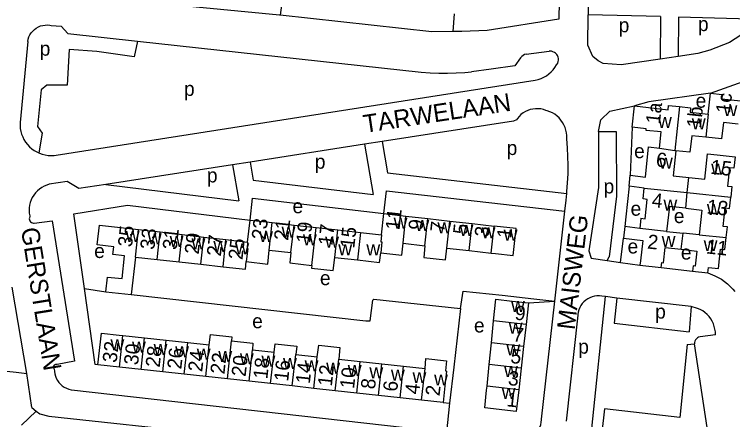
# Model space of a CAD drawing. Extents: x 161936 to 163647, y 386450 to 388633.
# Drawn here: x 162668.3 to 162869.1, y 387499.8 to 387613.3 of the extents above; entities that cross this region are included whole.
import ezdxf

# ---------------------------------------------------------------- set-up
doc = ezdxf.new("R2010")
doc.units = 0
for name, color, linetype in [('BLT_Basislijn', 7, 'Continuous'), ('BLT_Bebouwing', 7, 'Continuous'), ('BLT_Centroide', 7, 'Continuous'), ('BLT_Huisnummer', 7, 'Continuous'), ('BLT_Huisnummer_ tussenligend', 7, 'Continuous'), ('BLT_Onderverdeling_panden', 7, 'Continuous'), ('BLT_Straatnaam', 7, 'Continuous'), ('BLT_Vlakafsluiter', 7, 'Continuous')]:
    doc.layers.add(name, color=color, linetype=linetype)

msp = doc.modelspace()

# ---------------------------------------------------------------- linework, layer by layer
at = {"layer": 'BLT_Basislijn'}
for p, q in [((162743.31, 387618.68), (162742.58, 387613.02)), ((162828.78, 387617.69), (162828.68, 387613.16)), ((162790.95, 387608.44), (162791.33, 387613.38)), ((162848.91, 387612.62), (162828.68, 387613.16)), ((162848.91, 387612.62), (162848.83, 387600.77)), ((162853.91, 387612.48), (162853.84, 387601.51)), ((162672, 387605.68), (162669.87, 387583.02)), ((162702.71, 387605.79), (162782.04, 387597.12)), ((162811.38, 387602.17), (162817.8, 387602.93)), ((162853.84, 387601.51), (162848.83, 387600.77)), ((162679.94, 387573.88), (162813.91, 387594.86)), ((162766.13, 387576.91), (162734.19, 387571.94)), ((162771.08, 387577.68), (162766.13, 387576.91)), ((162766.13, 387576.91), (162768.57, 387562.84)), ((162771.08, 387577.68), (162772.59, 387568.91)), ((162734.19, 387571.94), (162729.25, 387571.17)), ((162734.19, 387571.94), (162735.06, 387566.88)), ((162729.25, 387571.17), (162693.83, 387565.67)), ((162729.25, 387571.17), (162730.99, 387561.05)), ((162772.59, 387568.91), (162822.7, 387563.16)), ((162735.06, 387566.88), (162768.57, 387562.84)), ((162693.83, 387565.67), (162730.99, 387561.05)), ((162822.49, 387561.28), (162822.7, 387563.16)), ((162822.14, 387558.19), (162822.49, 387561.28)), ((162819.34, 387532.99), (162822.14, 387558.19)), ((162837.74, 387543.83), (162838.58, 387550.62)), ((162833.95, 387544.36), (162834.57, 387545.42)), ((162833.95, 387544.36), (162837.74, 387543.83)), ((162837.74, 387543.83), (162843.17, 387543.06)), ((162849.13, 387542.39), (162857.84, 387541.42)), ((162671.73, 387512.76), (162667.69, 387536.93)), ((162829.67, 387497.33), (162833.54, 387534.27)), ((162833.54, 387534.27), (162832.48, 387534.39)), ((162836.74, 387533.89), (162833.54, 387534.27)), ((162836.74, 387533.89), (162835.93, 387526.84)), ((162857.52, 387531.55), (162836.74, 387533.89)), ((162815.66, 387499.97), (162819.34, 387532.99)), ((162857.52, 387531.55), (162856.92, 387524.43)), ((162825.8, 387529.05), (162822.49, 387499.42)), ((162835.93, 387526.84), (162856.92, 387524.43)), ((162864.26, 387523.62), (162859.95, 387523)), ((162856.37, 387520.88), (162858.36, 387521.03)), ((162861.93, 387497.67), (162858.36, 387521.03)), ((162673.18, 387503.23), (162671.73, 387512.76)), ((162684.27, 387508.21), (162789.12, 387496.33)), ((162788.15, 387504.68), (162789.94, 387504.45)), ((162670.29, 387498.35), (162674.4, 387502.25)), ((162673.18, 387503.23), (162674.4, 387502.25))]:
    msp.add_line(p, q, dxfattribs=at)
for points in [[(162796.15, 387657.6), (162798.19, 387657.39), (162818.08, 387655.25), (162820.47, 387653.11), (162821.27, 387651.11), (162820.44, 387611.92), (162800.48, 387608.77), (162793.38, 387608.47), (162790.95, 387608.44)], [(162742.58, 387613.02), (162742.44, 387613.03), (162667.7, 387620.29)], [(162790.95, 387608.44), (162784.97, 387608.38), (162742.58, 387613.02)], [(162848.83, 387600.77), (162837.92, 387599.14), (162832.86, 387599.51), (162831.52, 387600.27), (162830.02, 387601.45), (162828.56, 387604.68), (162828.68, 387613.16)], [(162876.09, 387610.55), (162874.08, 387611.94), (162853.91, 387612.48)], [(162672, 387605.68), (162672.13, 387606.33), (162672.34, 387606.95), (162672.62, 387607.54), (162672.98, 387608.09), (162673.4, 387608.6), (162673.88, 387609.05), (162674.4, 387609.44), (162674.98, 387609.76), (162675.58, 387610.01), (162676.22, 387610.18), (162676.87, 387610.28), (162677.52, 387610.3), (162678.18, 387610.23), (162678.52, 387610.17)], [(162678.52, 387610.17), (162681.37, 387609.97), (162683.2, 387607.93), (162702.71, 387605.79)], [(162876.09, 387610.55), (162868.22, 387605.43), (162862.65, 387603.23), (162859.31, 387602.33), (162853.84, 387601.51)], [(162702.71, 387605.79), (162701.75, 387601.4), (162691.33, 387602.86), (162683.61, 387603.44), (162683.01, 387593.48), (162677.37, 387593.42), (162675.74, 387592.18), (162674.71, 387581.89), (162676.02, 387580.02), (162675.15, 387574.47)], [(162811.38, 387602.17), (162810.93, 387602.01), (162810.52, 387601.78), (162810.14, 387601.48), (162809.8, 387601.1)], [(162819.94, 387599.26), (162820.16, 387599.63), (162820.31, 387600.04), (162820.38, 387600.46), (162820.37, 387600.89), (162820.28, 387601.31), (162820.12, 387601.71), (162819.88, 387602.07), (162819.59, 387602.38), (162819.24, 387602.63), (162818.85, 387602.81), (162818.43, 387602.92), (162818, 387602.95), (162817.8, 387602.93)], [(162809.8, 387601.1), (162808.17, 387598.85), (162801.6, 387597.89), (162796.1, 387597.17)], [(162862.91, 387591.19), (162875.97, 387595.89), (162884.46, 387600.33), (162888.82, 387601.21), (162889.7, 387601.21)], [(162813.91, 387594.86), (162814.73, 387595.06), (162815.52, 387595.33), (162816.28, 387595.68), (162817, 387596.1), (162817.68, 387596.59), (162818.31, 387597.14), (162818.89, 387597.74), (162819.4, 387598.4), (162819.86, 387599.11), (162819.94, 387599.26)], [(162782.04, 387597.12), (162784.48, 387596.94), (162786.92, 387596.84), (162789.36, 387596.82), (162791.8, 387596.87), (162794.24, 387597.01), (162796.1, 387597.17)], [(162862.91, 387591.19), (162845.67, 387588.78), (162841.59, 387587.63)], [(162816.86, 387586.4), (162816.16, 387586.64), (162815.43, 387586.79), (162814.7, 387586.87), (162813.96, 387586.86), (162813.22, 387586.78), (162812.5, 387586.62), (162811.8, 387586.38), (162811.12, 387586.07), (162810.49, 387585.68), (162809.9, 387585.23), (162809.37, 387584.72), (162808.89, 387584.16), (162808.62, 387583.79)], [(162822.69, 387578.56), (162822.69, 387579.35), (162822.61, 387580.13), (162822.45, 387580.89), (162822.21, 387581.64), (162821.9, 387582.36), (162821.51, 387583.04), (162821.06, 387583.68), (162820.55, 387584.28), (162819.97, 387584.81), (162819.35, 387585.29), (162818.68, 387585.7), (162817.98, 387586.03), (162817.24, 387586.3), (162816.86, 387586.4)], [(162831.53, 387580.5), (162832.25, 387583.72), (162834.73, 387586.17), (162841.59, 387587.63)], [(162808.62, 387583.79), (162807.82, 387583.39), (162771.08, 387577.68)], [(162669.87, 387583.02), (162669.86, 387582.19), (162669.92, 387581.35), (162670.07, 387580.53), (162670.3, 387579.73), (162670.6, 387578.95), (162670.97, 387578.2), (162671.42, 387577.5), (162671.92, 387576.84), (162672.49, 387576.23), (162673.12, 387575.68), (162673.8, 387575.19), (162674.52, 387574.76), (162675.15, 387574.47)], [(162831.53, 387580.5), (162831.61, 387564.84), (162828.88, 387547.07), (162829.54, 387545.03), (162833.95, 387544.36)], [(162831.53, 387580.5), (162836.5, 387580.52), (162836.62, 387562.37), (162834.57, 387545.42)], [(162840.96, 387581.68), (162840.46, 387568.22)], [(162822.7, 387563.16), (162822.76, 387563.71), (162822.95, 387566.16), (162823.06, 387568.6), (162823.09, 387571.05), (162823.04, 387573.5), (162822.91, 387575.95), (162822.71, 387578.39), (162822.69, 387578.56)], [(162675.15, 387574.47), (162675.27, 387574.41), (162676.06, 387574.13), (162676.87, 387573.93), (162677.7, 387573.81), (162678.53, 387573.77), (162679.36, 387573.8), (162679.94, 387573.88)], [(162678.04, 387565.7), (162677.31, 387565.48), (162676.6, 387565.18), (162675.92, 387564.82), (162675.29, 387564.38), (162674.7, 387563.88), (162674.17, 387563.32), (162673.7, 387562.71), (162673.3, 387562.06), (162672.96, 387561.36), (162672.7, 387560.64), (162672.52, 387559.89), (162672.41, 387559.13), (162672.39, 387558.36), (162672.44, 387557.6), (162672.58, 387556.84), (162672.62, 387556.66)], [(162693.83, 387565.67), (162686.28, 387564.49), (162683.07, 387566.5), (162678.04, 387565.7)], [(162771.56, 387557.51), (162772.3, 387563.91), (162822.14, 387558.19)], [(162840.11, 387565.17), (162839.23, 387556.63), (162838.95, 387553.9)], [(162734.16, 387555.66), (162734.85, 387561.87), (162771.56, 387557.51)], [(162687.86, 387536.56), (162684.87, 387557.46), (162699.94, 387559.87), (162734.16, 387555.66)], [(162672.62, 387556.66), (162672.5, 387556.37), (162672.46, 387556.06), (162672.5, 387555.75), (162672.61, 387555.46), (162672.8, 387555.21), (162673.04, 387555.02), (162673.32, 387554.89), (162673.63, 387554.84), (162673.82, 387554.85)], [(162673.82, 387554.85), (162678.85, 387555.45), (162685.07, 387516.25), (162680.25, 387515.25)], [(162862.14, 387540.94), (162864.05, 387540.13), (162865, 387539.67), (162865.92, 387539.14), (162866.79, 387538.54), (162867.62, 387537.87), (162868.4, 387537.15), (162869.11, 387536.37), (162869.66, 387535.69)], [(162691.64, 387515.16), (162690.9, 387515.25), (162687.86, 387536.56)], [(162687.86, 387536.56), (162693.82, 387535.64)], [(162793.03, 387530.99), (162793.71, 387535.83), (162804.67, 387534.64), (162813.46, 387533.64), (162819.34, 387532.99)], [(162700.95, 387534.86), (162766.51, 387527.54), (162767.78, 387527.49), (162768.48, 387533.25), (162768.73, 387533.53), (162793.03, 387530.99)], [(162832.48, 387534.39), (162831.81, 387534.47), (162831.14, 387534.46), (162830.46, 387534.38), (162829.81, 387534.22), (162829.18, 387533.98), (162828.58, 387533.67), (162828.02, 387533.29), (162827.51, 387532.84), (162827.05, 387532.34), (162826.66, 387531.79), (162826.34, 387531.2), (162826.09, 387530.57), (162825.91, 387529.92), (162825.81, 387529.25), (162825.8, 387529.05)], [(162864.26, 387523.62), (162864.24, 387524.41), (162864.13, 387525.18), (162863.94, 387525.95), (162863.68, 387526.69), (162863.34, 387527.41), (162862.93, 387528.08), (162862.46, 387528.71), (162861.93, 387529.29), (162861.34, 387529.81), (162860.7, 387530.27), (162860.01, 387530.66), (162859.29, 387530.98), (162857.52, 387531.55)], [(162793.03, 387530.99), (162791.14, 387514.5), (162789.94, 387504.45)], [(162859.95, 387523), (162859.57, 387522.89), (162859.22, 387522.71), (162858.92, 387522.45), (162858.67, 387522.15), (162858.49, 387521.79), (162858.38, 387521.41), (162858.36, 387521.03)], [(162856.37, 387520.88), (162854.26, 387500.47), (162833.24, 387502.91), (162832.51, 387496.26)], [(162648.95, 387510.13), (162649.61, 387515.1), (162660.06, 387514.06), (162668.81, 387513.1), (162671.73, 387512.76)], [(162680.25, 387515.25), (162680.02, 387515.32), (162679.78, 387515.31), (162679.56, 387515.22), (162679.37, 387515.06), (162679.25, 387514.85), (162679.2, 387514.62), (162679.23, 387514.38), (162679.34, 387514.16), (162679.45, 387514.04)], [(162679.45, 387514.04), (162679.47, 387513.37), (162679.57, 387512.7), (162679.74, 387512.04), (162680, 387511.42), (162680.32, 387510.82), (162680.72, 387510.27), (162681.17, 387509.77), (162681.68, 387509.33), (162682.24, 387508.95), (162682.85, 387508.64), (162683.48, 387508.4), (162684.14, 387508.24), (162684.27, 387508.21)], [(162789.94, 387504.45), (162789.12, 387496.33)], [(162674.4, 387502.25), (162675.36, 387501.47), (162677.9, 387500.85), (162722.89, 387495.99), (162725.51, 387494.85), (162727.19, 387492.41), (162727.19, 387489.31)], [(162808.42, 387494.15), (162809.11, 387494.05), (162809.81, 387494.03), (162810.5, 387494.09), (162811.18, 387494.23), (162811.84, 387494.45), (162812.47, 387494.74), (162813.06, 387495.1), (162813.61, 387495.53), (162814.1, 387496.02), (162814.54, 387496.56), (162814.91, 387497.15), (162815.21, 387497.78), (162815.43, 387498.43), (162815.58, 387499.11), (162815.65, 387499.8), (162815.66, 387499.97)]]:
    msp.add_lwpolyline(points, dxfattribs=at)
at = {"layer": 'BLT_Bebouwing'}
for p, q in [((162862.26, 387585.33), (162862.91, 387591.19)), ((162840.96, 387581.68), (162841.59, 387587.63)), ((162733.48, 387549.55), (162734.16, 387555.66)), ((162734.16, 387555.66), (162740.33, 387554.98)), ((162770.9, 387551.59), (162771.56, 387557.51)), ((162771.56, 387557.51), (162777.75, 387556.83)), ((162777.75, 387556.83), (162783.87, 387556.15)), ((162783.87, 387556.15), (162790.05, 387555.39)), ((162843.4, 387556.19), (162843.08, 387553.37)), ((162740.33, 387554.98), (162746.45, 387554.3)), ((162746.45, 387554.3), (162752.64, 387553.61)), ((162790.05, 387555.39), (162796.22, 387554.71)), ((162796.22, 387554.71), (162802.39, 387554.02)), ((162843.08, 387553.37), (162838.95, 387553.9)), ((162702.96, 387553.06), (162709.04, 387552.38)), ((162709.04, 387552.38), (162715.22, 387551.68)), ((162715.22, 387551.68), (162721.27, 387550.94)), ((162752.64, 387553.61), (162758.68, 387552.93)), ((162758.68, 387552.93), (162765.03, 387552.24)), ((162765.03, 387552.24), (162770.9, 387551.59)), ((162850.62, 387552.52), (162855.24, 387552)), ((162859.67, 387551.56), (162855.24, 387552)), ((162721.27, 387550.94), (162727.37, 387550.23)), ((162727.37, 387550.23), (162733.48, 387549.55)), ((162776.94, 387549.19), (162783.04, 387548.52)), ((162789.21, 387547.83), (162795.38, 387547.15)), ((162739.53, 387547.27), (162745.61, 387546.59)), ((162795.38, 387547.15), (162801.56, 387546.47)), ((162702.11, 387545.36), (162708.19, 387544.69)), ((162708.19, 387544.69), (162714.37, 387544)), ((162714.37, 387544), (162720.45, 387543.33)), ((162757.84, 387545.24), (162764.19, 387544.53)), ((162843.31, 387544.32), (162843.17, 387543.06)), ((162720.45, 387543.33), (162726.61, 387542.65)), ((162843.17, 387543.06), (162849.13, 387542.39)), ((162862.31, 387542.41), (162865.11, 387542.11)), ((162693.82, 387535.64), (162700.95, 387534.86)), ((162801.65, 387521.37), (162802.26, 387527.46)), ((162811.34, 387526.43), (162810.65, 387520.35)), ((162691.64, 387515.16), (162692.61, 387524.04)), ((162698.64, 387523.38), (162704.67, 387522.72)), ((162704.67, 387522.72), (162710.7, 387522.06)), ((162710.7, 387522.06), (162716.73, 387521.4)), ((162716.73, 387521.4), (162722.76, 387520.74)), ((162801.03, 387515.29), (162801.65, 387521.37)), ((162810.65, 387520.35), (162809.97, 387514.28)), ((162734.83, 387519.41), (162740.89, 387518.75)), ((162746.97, 387518.08), (162752.92, 387517.43)), ((162758.95, 387516.77), (162764.98, 387516.11)), ((162764.98, 387516.11), (162771.01, 387515.45)), ((162697.68, 387514.51), (162691.64, 387515.16)), ((162703.71, 387513.85), (162697.68, 387514.51)), ((162709.74, 387513.2), (162703.71, 387513.85)), ((162771.01, 387515.45), (162777.05, 387514.79)), ((162777.05, 387514.79), (162783.08, 387514.12)), ((162800.41, 387509.2), (162801.03, 387515.29)), ((162809.97, 387514.28), (162809.28, 387508.2)), ((162715.77, 387512.54), (162709.74, 387513.2)), ((162721.8, 387511.89), (162715.77, 387512.54)), ((162727.84, 387511.23), (162721.8, 387511.89)), ((162733.87, 387510.58), (162727.84, 387511.23)), ((162739.9, 387509.92), (162733.87, 387510.58)), ((162745.93, 387509.27), (162739.9, 387509.92)), ((162751.96, 387508.61), (162745.93, 387509.27)), ((162757.99, 387507.96), (162751.96, 387508.61)), ((162764.03, 387507.3), (162757.99, 387507.96)), ((162770.06, 387506.65), (162764.03, 387507.3)), ((162776.09, 387505.99), (162770.06, 387506.65)), ((162782.12, 387505.34), (162776.09, 387505.99))]:
    msp.add_line(p, q, dxfattribs=at)
for points in [[(162862.91, 387591.19), (162866.17, 387590.83), (162866.04, 387589.6), (162871.31, 387589.02)], [(162841.59, 387587.63), (162851.04, 387586.58), (162851.18, 387587.8), (162854.25, 387587.46)], [(162854.25, 387587.46), (162857.33, 387587.11), (162857.2, 387585.89), (162862.26, 387585.33)], [(162870.59, 387582.55), (162866.48, 387583), (162865.98, 387578.39), (162861.54, 387578.87)], [(162848.6, 387575.86), (162849.07, 387580.36), (162844.87, 387580.81), (162844.92, 387581.26), (162840.96, 387581.68)], [(162861.54, 387578.87), (162857.63, 387579.29), (162857.13, 387574.69), (162853.19, 387575.12)], [(162840.46, 387568.22), (162844.7, 387567.75), (162845.59, 387576.18), (162848.6, 387575.86)], [(162853.19, 387575.12), (162852.43, 387568.1), (162856.82, 387567.62)], [(162856.82, 387567.62), (162861.28, 387567.14), (162862.05, 387574.27), (162864.78, 387573.97), (162869.75, 387573.43), (162869.4, 387570.23), (162868.18, 387570.36), (162867.62, 387565.22), (162868.84, 387565.09), (162868.52, 387562.12)], [(162840.11, 387565.17), (162840.46, 387568.22)], [(162844.37, 387564.67), (162840.11, 387565.17)], [(162843.4, 387556.19), (162844.64, 387556.06), (162845.21, 387561.48), (162844.05, 387561.6), (162844.37, 387564.67)], [(162867.29, 387550.82), (162867.62, 387553.8), (162866.4, 387553.93), (162866.95, 387559.08), (162868.18, 387558.94), (162868.52, 387562.12)], [(162855.96, 387559), (162851.39, 387559.5), (162850.62, 387552.52)], [(162855.96, 387559), (162860.41, 387558.51), (162859.67, 387551.56)], [(162693.82, 387535.64), (162694.27, 387539.76), (162698.37, 387539.31), (162699.07, 387545.7), (162695.84, 387546.05), (162696.08, 387548.23), (162691.45, 387548.75), (162692.06, 387554.27), (162702.96, 387553.06)], [(162801.56, 387546.47), (162802.75, 387546.33), (162807.72, 387545.78), (162808.56, 387553.34), (162802.39, 387554.02)], [(162838.95, 387553.9), (162838.58, 387550.62)], [(162838.58, 387550.62), (162843.94, 387549.96), (162843.31, 387544.32)], [(162865.11, 387542.11), (162865.7, 387547.56), (162866.93, 387547.43), (162867.29, 387550.82)], [(162770.69, 387546.57), (162776.59, 387545.92), (162776.94, 387549.19)], [(162783.04, 387548.52), (162782.71, 387545.24), (162788.8, 387544.57), (162789.21, 387547.83)], [(162849.77, 387543.77), (162850.23, 387548), (162854.65, 387547.52)], [(162733.12, 387544.06), (162739.13, 387543.39), (162739.53, 387547.27)], [(162745.61, 387546.59), (162745.31, 387543.71), (162751.42, 387543.03)], [(162764.19, 387544.53), (162770.38, 387543.85), (162770.69, 387546.57)], [(162854.65, 387547.52), (162859.07, 387547.04), (162858.61, 387542.81), (162858, 387542.85), (162857.84, 387541.42)], [(162702.11, 387545.36), (162700.95, 387534.86)], [(162726.61, 387542.65), (162732.89, 387541.95), (162733.12, 387544.06)], [(162751.42, 387543.03), (162751.33, 387542.24), (162757.44, 387541.56), (162757.84, 387545.24)], [(162849.13, 387542.39), (162849.29, 387543.82), (162849.77, 387543.77)], [(162862.14, 387540.94), (162862.31, 387542.41)], [(162857.84, 387541.42), (162862.14, 387540.94)], [(162802.26, 387527.46), (162802.88, 387533.54), (162807.43, 387533.02), (162812.03, 387532.5)], [(162812.03, 387532.5), (162811.34, 387526.43)], [(162692.61, 387524.04), (162697.58, 387523.5), (162698.64, 387523.38)], [(162722.76, 387520.74), (162723.08, 387523.68), (162729.08, 387523.02), (162729, 387521.93)], [(162729, 387521.93), (162734.98, 387521.27), (162734.83, 387519.41)], [(162740.89, 387518.75), (162741.15, 387521.09), (162747.23, 387520.43), (162746.97, 387518.08)], [(162752.92, 387517.43), (162753.38, 387520.7), (162759.22, 387520.06), (162758.95, 387516.77)], [(162783.08, 387514.12), (162783.31, 387516.92), (162789.11, 387516.28), (162788.8, 387513.5), (162789.11, 387513.46), (162788.65, 387509.28), (162788.15, 387504.68)], [(162799.79, 387503.12), (162800.3, 387508.1), (162800.41, 387509.2)], [(162809.28, 387508.2), (162808.59, 387502.12), (162799.79, 387503.12)], [(162788.15, 387504.68), (162782.12, 387505.34)]]:
    msp.add_lwpolyline(points, dxfattribs=at)
at = {"layer": 'BLT_Onderverdeling_panden'}
for p, q in [((162854.25, 387587.46), (162852.89, 387575.17)), ((162862.26, 387585.33), (162861.54, 387578.87)), ((162848.6, 387575.86), (162852.89, 387575.17)), ((162852.89, 387575.17), (162853.19, 387575.12)), ((162856.38, 387563.4), (162856.82, 387567.62)), ((162844.37, 387564.67), (162856.38, 387563.4)), ((162855.96, 387559), (162856.38, 387563.4)), ((162856.38, 387563.4), (162868.52, 387562.12)), ((162776.94, 387549.19), (162777.75, 387556.83)), ((162783.04, 387548.52), (162783.87, 387556.15)), ((162739.53, 387547.27), (162740.33, 387554.98)), ((162745.61, 387546.59), (162746.45, 387554.3)), ((162789.21, 387547.83), (162790.05, 387555.39)), ((162795.38, 387547.15), (162796.22, 387554.71)), ((162801.56, 387546.47), (162802.39, 387554.02)), ((162702.11, 387545.36), (162702.96, 387553.06)), ((162708.19, 387544.69), (162709.04, 387552.38)), ((162714.37, 387544), (162715.22, 387551.68)), ((162751.42, 387543.03), (162752.64, 387553.61)), ((162757.84, 387545.24), (162758.68, 387552.93)), ((162765.03, 387552.24), (162764.19, 387544.53)), ((162850.62, 387552.52), (162843.08, 387553.37)), ((162854.65, 387547.52), (162855.24, 387552)), ((162720.45, 387543.33), (162721.27, 387550.94)), ((162726.61, 387542.65), (162727.37, 387550.23)), ((162859.67, 387551.56), (162867.29, 387550.82)), ((162811.34, 387526.43), (162802.26, 387527.46)), ((162697.68, 387514.51), (162698.64, 387523.38)), ((162703.71, 387513.85), (162704.67, 387522.72)), ((162709.74, 387513.2), (162710.7, 387522.06)), ((162727.84, 387511.23), (162729, 387521.93)), ((162715.77, 387512.54), (162716.73, 387521.4)), ((162721.8, 387511.89), (162722.76, 387520.74)), ((162810.65, 387520.35), (162801.65, 387521.37)), ((162733.87, 387510.58), (162734.83, 387519.41)), ((162739.9, 387509.92), (162740.89, 387518.75)), ((162745.93, 387509.27), (162746.97, 387518.08)), ((162751.96, 387508.61), (162752.92, 387517.43)), ((162757.99, 387507.96), (162758.95, 387516.77)), ((162764.03, 387507.3), (162764.98, 387516.11)), ((162770.06, 387506.65), (162771.01, 387515.45)), ((162776.09, 387505.99), (162777.05, 387514.79)), ((162782.12, 387505.34), (162783.08, 387514.12)), ((162809.97, 387514.28), (162801.03, 387515.29)), ((162809.28, 387508.2), (162800.41, 387509.2))]:
    msp.add_line(p, q, dxfattribs=at)
for points in [[(162770.9, 387551.59), (162770.74, 387549.65), (162771.02, 387549.63), (162770.69, 387546.57)], [(162733.48, 387549.55), (162733.38, 387547.78), (162733.5, 387547.77), (162733.12, 387544.06)]]:
    msp.add_lwpolyline(points, dxfattribs=at)
at = {"layer": 'BLT_Vlakafsluiter'}
msp.add_line((162812.03, 387532.5), (162819.34, 387532.99), dxfattribs=at)

# ---------------------------------------------------------------- texts
at = {"layer": 'BLT_Centroide'}
for s, p in [('p', (162837.22, 387608.25)), ('p', (162859.37, 387608.58)), ('p', (162675.36, 387601.7)), ('p', (162715.7, 387590.45)), ('e', (162858.73, 387587.13)), ('w', (162866.52, 387584.78)), ('w', (162848.21, 387581.47)), ('w', (162857.66, 387581.06)), ('p', (162805.9, 387573.9)), ('e', (162841.53, 387573.02)), ('p', (162752.27, 387570.07)), ('w', (162848.47, 387570.06)), ('w', (162863.06, 387568.42)), ('p', (162722.1, 387566.23)), ('p', (162832.99, 387563.15)), ('e', (162746.04, 387557.61)), ('e', (162840.54, 387556.92)), ('w', (162849.73, 387558.36)), ('w', (162861.88, 387557.08)), ('e', (162852.63, 387554.86)), ('w', (162774.3, 387553.31)), ('w', (162780.38, 387552.64)), ('w', (162742.98, 387550.78)), ('w', (162786.55, 387551.95)), ('w', (162792.72, 387551.27)), ('w', (162798.89, 387550.58)), ('w', (162699.41, 387549.56)), ('w', (162705.58, 387548.88)), ('w', (162736.72, 387549.52)), ('w', (162748.95, 387548.61)), ('w', (162805.06, 387549.91)), ('w', (162711.7, 387548.19)), ('w', (162717.81, 387547.5)), ('w', (162723.91, 387546.78)), ('w', (162755.16, 387547.94)), ('w', (162849.23, 387548.16)), ('w', (162860.97, 387547)), ('e', (162690.59, 387545.08)), ('w', (162730.05, 387546.09)), ('w', (162758.84, 387545.81)), ('w', (162766.69, 387545.81)), ('e', (162839.7, 387546.35)), ('e', (162854.6, 387544.66)), ('e', (162753.7, 387537.49)), ('w', (162807.12, 387529.97)), ('p', (162847.41, 387528.12)), ('e', (162734.76, 387525.43)), ('e', (162796.76, 387524.25)), ('w', (162806.48, 387523.91)), ('w', (162695.14, 387519.27)), ('w', (162701.17, 387518.61)), ('w', (162707.2, 387517.95)), ('w', (162713.23, 387517.3)), ('w', (162719.27, 387516.64)), ('w', (162805.82, 387517.81)), ('p', (162825.9, 387518.31)), ('w', (162725.3, 387515.98)), ('w', (162731.33, 387515.33)), ('w', (162737.36, 387514.66)), ('w', (162743.39, 387514)), ('w', (162749.42, 387513.34)), ('w', (162755.45, 387512.7)), ('w', (162761.48, 387512.05)), ('w', (162767.52, 387511.39)), ('w', (162773.55, 387510.72)), ('w', (162805.17, 387511.75)), ('w', (162779.58, 387510.06)), ('w', (162785.61, 387509.41)), ('w', (162804.52, 387505.66))]:
    msp.add_text(s, height=4, dxfattribs=at).set_placement(p)
at = {"layer": 'BLT_Huisnummer'}
for s, rotation, p in [('1c', 83.6442, (162868.31, 387585.43)), ('1a', 83.6537, (162848.72, 387582.47)), ('1b', 83.653, (162860.16, 387581.34)), ('6', 353.9654, (162847.5, 387570.72)), ('15', 353.9654, (162862.74, 387568.67)), ('4', 353.9622, (162846.34, 387559.36)), ('13', 353.9612, (162861.69, 387557.55)), ('9', 83.7047, (162782.35, 387552.74)), ('35', 83.6756, (162701.14, 387548.02)), ('21', 83.7549, (162744.79, 387549.85)), ('17', 83.7615, (162757.19, 387548.43)), ('5', 83.7056, (162794.84, 387551.52)), ('29', 83.6764, (162719.8, 387545.98)), ('1', 83.6715, (162807.12, 387550.43)), ('2', 353.6271, (162845.08, 387547.76)), ('25', 83.6724, (162732.04, 387544.46)), ('11', 353.8117, (162861.53, 387546.38)), ('9', 353.5468, (162808.01, 387527.86)), ('32', 83.801, (162696.86, 387515.65)), ('26', 83.8048, (162714.94, 387513.84)), ('5', 353.5473, (162806.83, 387515.73)), ('22', 83.8028, (162727, 387512.46)), ('18', 83.8002, (162738.99, 387511.08)), ('14', 83.8047, (162750.86, 387509.76)), ('10', 83.8027, (162763.23, 387508.39)), ('6', 83.8001, (162775.27, 387507.57)), ('2', 83.8118, (162787.13, 387506.32)), ('1', 353.5483, (162805.77, 387503.62))]:
    msp.add_text(s, height=4, rotation=rotation, dxfattribs=at).set_placement(p)
at = {"layer": 'BLT_Huisnummer_ tussenligend'}
for s, rotation, p in [('11', 83.7047, (162775.94, 387552.77)), ('23', 83.7549, (162738.53, 387550.05)), ('19', 83.7615, (162750.98, 387549.09)), ('7', 83.7056, (162788.46, 387552.16)), ('3', 83.6715, (162800.86, 387550.81)), ('33', 83.6764, (162707.38, 387547.29)), ('31', 83.6764, (162713.64, 387547.25)), ('15', 83.6829, (162763.29, 387547.67)), ('27', 83.6724, (162725.99, 387545.42)), ('7', 353.5473, (162807.47, 387521.79)), ('30', 83.8048, (162702.84, 387514.99)), ('28', 83.8048, (162708.89, 387514.34)), ('24', 83.8028, (162720.78, 387513.1)), ('20', 83.8002, (162732.91, 387511.76)), ('16', 83.8047, (162744.81, 387510.42)), ('12', 83.8027, (162757.02, 387509.06)), ('3', 353.5483, (162806.15, 387509.56)), ('8', 83.8001, (162769.06, 387508.23)), ('4', 83.8118, (162781.41, 387506.8))]:
    msp.add_text(s, height=4, rotation=rotation, dxfattribs=at).set_placement(p)
at = {"layer": 'BLT_Straatnaam'}
for s, rotation, p in [('TARWELAAN', 8.6191, (162766.22, 387580.09)), ('MAISWEG', 83.2561, (162824.91, 387524.82)), ('GERSTLAAN', 279.1734, (162670.11, 387553.24))]:
    msp.add_text(s, height=5, rotation=rotation, dxfattribs=at).set_placement(p)

doc.saveas('drawing.dxf')
